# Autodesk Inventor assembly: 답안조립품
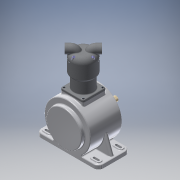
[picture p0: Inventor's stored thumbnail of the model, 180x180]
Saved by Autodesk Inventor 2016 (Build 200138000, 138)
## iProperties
Created: 2015-06
Part Number: 답안조립품
Document SubType Name: Assembly
Designer: Administrator
Author: Administrator
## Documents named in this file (15)
- C:\Users\Administrator\Desktop\450606V1010\답안조립품.iam
- C:\Users\Administrator\Desktop\450606V1010\본체.ipt
- C:\Users\Administrator\Desktop\450606V1010\베어링 6204.ipt
- C:\Users\Administrator\Desktop\450606V1010\메인커버.ipt
- C:\Users\Administrator\Desktop\450606V1010\메인 크랭크 축-구동부.ipt
- C:\Users\Administrator\Desktop\450606V1010\크랭크 서브축.ipt
- C:\Users\Administrator\Desktop\450606V1010\베어링 NA 4902.ipt
- C:\Users\Administrator\Desktop\450606V1010\커넥팅 로드.ipt
- C:\Users\Administrator\Desktop\450606V1010\피스톤 핀.ipt
- C:\Users\Administrator\Desktop\450606V1010\피스톤.ipt
- C:\Users\Administrator\Desktop\450606V1010\실린더.ipt
- C:\Users\Administrator\Desktop\450606V1010\실린더헤드.ipt
- C:\Users\Administrator\Desktop\450606V1010\오일실.ipt
- C:\Users\Administrator\Desktop\450606V1010\M5x0.8.ipt
- C:\Users\Administrator\Desktop\450606V1010\M4x0.7.ipt
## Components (14 placed, 4 different names)
1. 피스톤 핀:1
2. 피스톤:1
3. M4x0.7:1
4. M4x0.7:2
5. M4x0.7:3
6. M4x0.7:4
7. M5x0.8:1
8. M5x0.8:2
9. M5x0.8:3
10. M5x0.8:4
11. M4x0.7:5
12. M4x0.7:6
13. M4x0.7:7
14. M4x0.7:8
